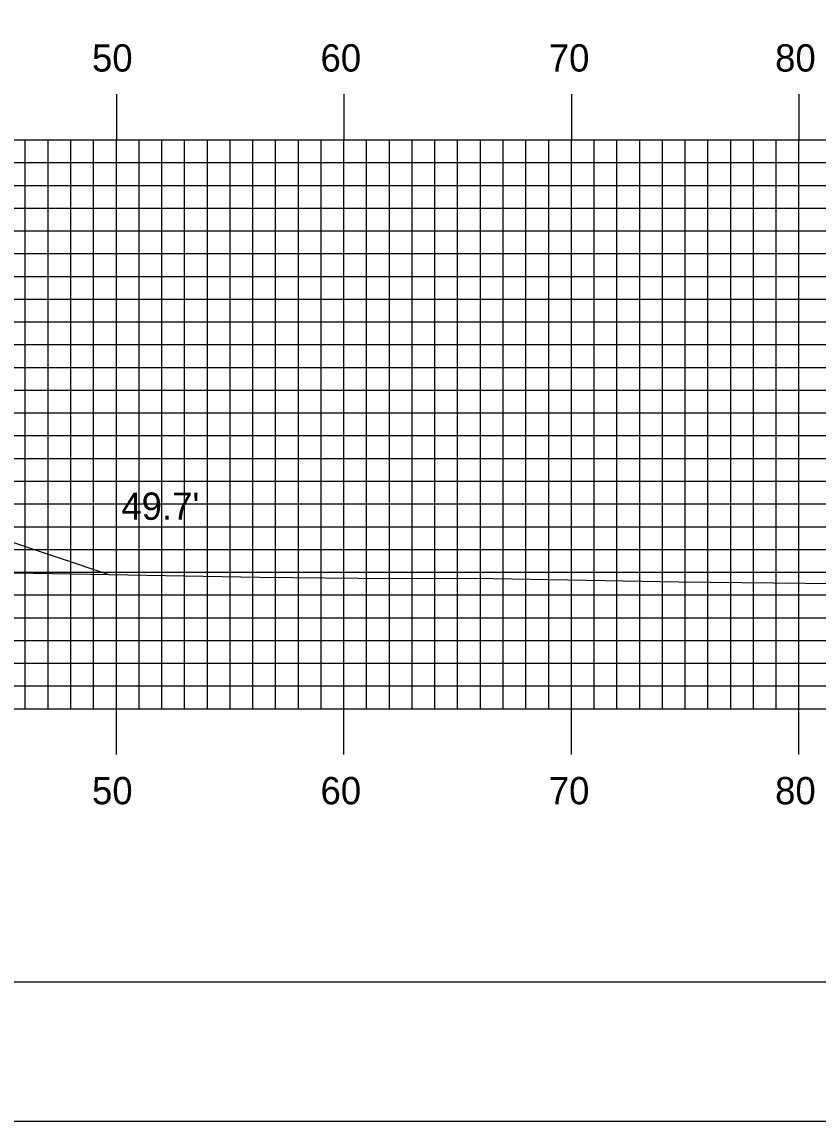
# Model space of a CAD drawing. Extents: x 856323 to 856666, y 364765 to 364985.
# Drawn here: x 856534.62 to 856569.6, y 364765.18 to 364813.48 of the extents above; entities that cross this region are included whole.
import ezdxf

# ---------------------------------------------------------------- set-up
doc = ezdxf.new("R2010")
doc.units = 0
for name, color, linetype in [('BORDER', 7, 'Continuous'), ('D_Roadway_Centerline', 7, 'Continuous'), ('D_Roadway_SlopeLines', 7, 'Continuous'), ('D_Text_Standard', 7, 'Continuous'), ('H_V ANNOTATION', 7, 'Continuous'), ('MAJOR', 7, 'Continuous'), ('MINOR', 7, 'Continuous'), ('PLOT BOUNDARY', 7, 'Continuous'), ('S_Roadway_Centerline', 7, 'Continuous')]:
    doc.layers.add(name, color=color, linetype=linetype)

msp = doc.modelspace()

# ---------------------------------------------------------------- linework, layer by layer
at = {"layer": 'BORDER'}
msp.add_lwpolyline([(856339.168, 364771.302), (856659.168, 364771.302), (856659.168, 364981.302), (856339.168, 364981.302)], close=True, dxfattribs=at)
at = {"layer": 'D_Roadway_Centerline'}
msp.add_lwpolyline([(856476.768, 364802.881), (856476.768, 364802.881), (856488.768, 364802.411), (856496.768, 364802.091), (856508.768, 364799.091), (856509.389, 364798.935), (856538.439, 364789.201), (856538.441, 364789.2)], dxfattribs=at)
at = {"layer": 'D_Roadway_SlopeLines'}
msp.add_lwpolyline([(856496.768, 364802.091), (856509.389, 364798.935), (856538.441, 364789.2)], dxfattribs=at)
at = {"layer": 'MAJOR'}
for p, q in [((856538.768, 364810.306), (856538.768, 364808.302)), ((856548.768, 364810.306), (856548.768, 364808.302)), ((856558.768, 364810.306), (856558.768, 364808.302)), ((856568.768, 364810.306), (856568.768, 364808.302)), ((856348.768, 364808.302), (856628.768, 364808.302)), ((856348.768, 364808.302), (856628.768, 364808.302)), ((856538.768, 364783.302), (856538.768, 364808.302)), ((856548.768, 364783.302), (856548.768, 364808.302)), ((856558.768, 364783.302), (856558.768, 364808.302)), ((856568.768, 364783.302), (856568.768, 364808.302)), ((856348.768, 364803.302), (856628.768, 364803.302)), ((856348.768, 364798.302), (856628.768, 364798.302)), ((856348.768, 364793.302), (856628.768, 364793.302)), ((856348.768, 364788.302), (856628.768, 364788.302)), ((856348.768, 364783.302), (856628.768, 364783.302)), ((856348.768, 364783.302), (856628.768, 364783.302)), ((856538.768, 364781.298), (856538.768, 364783.302)), ((856548.768, 364781.298), (856548.768, 364783.302)), ((856558.768, 364781.298), (856558.768, 364783.302)), ((856568.768, 364781.298), (856568.768, 364783.302))]:
    msp.add_line(p, q, dxfattribs=at)
at = {"layer": 'MINOR'}
for p, q in [((856534.768, 364783.302), (856534.768, 364808.302)), ((856535.768, 364783.302), (856535.768, 364808.302)), ((856536.768, 364783.302), (856536.768, 364808.302)), ((856537.768, 364783.302), (856537.768, 364808.302)), ((856539.768, 364783.302), (856539.768, 364808.302)), ((856540.768, 364783.302), (856540.768, 364808.302)), ((856541.768, 364783.302), (856541.768, 364808.302)), ((856542.768, 364783.302), (856542.768, 364808.302)), ((856543.768, 364783.302), (856543.768, 364808.302)), ((856544.768, 364783.302), (856544.768, 364808.302)), ((856545.768, 364783.302), (856545.768, 364808.302)), ((856546.768, 364783.302), (856546.768, 364808.302)), ((856547.768, 364783.302), (856547.768, 364808.302)), ((856549.768, 364783.302), (856549.768, 364808.302)), ((856550.768, 364783.302), (856550.768, 364808.302)), ((856551.768, 364783.302), (856551.768, 364808.302)), ((856552.768, 364783.302), (856552.768, 364808.302)), ((856553.768, 364783.302), (856553.768, 364808.302)), ((856554.768, 364783.302), (856554.768, 364808.302)), ((856555.768, 364783.302), (856555.768, 364808.302)), ((856556.768, 364783.302), (856556.768, 364808.302)), ((856557.768, 364783.302), (856557.768, 364808.302)), ((856559.768, 364783.302), (856559.768, 364808.302)), ((856560.768, 364783.302), (856560.768, 364808.302)), ((856561.768, 364783.302), (856561.768, 364808.302)), ((856562.768, 364783.302), (856562.768, 364808.302)), ((856563.768, 364783.302), (856563.768, 364808.302)), ((856564.768, 364783.302), (856564.768, 364808.302)), ((856565.768, 364783.302), (856565.768, 364808.302)), ((856566.768, 364783.302), (856566.768, 364808.302)), ((856567.768, 364783.302), (856567.768, 364808.302)), ((856348.768, 364807.302), (856628.768, 364807.302)), ((856348.768, 364806.302), (856628.768, 364806.302)), ((856348.768, 364805.302), (856628.768, 364805.302)), ((856348.768, 364804.302), (856628.768, 364804.302)), ((856348.768, 364802.302), (856628.768, 364802.302)), ((856348.768, 364801.302), (856628.768, 364801.302)), ((856348.768, 364800.302), (856628.768, 364800.302)), ((856348.768, 364799.302), (856628.768, 364799.302)), ((856348.768, 364797.302), (856628.768, 364797.302)), ((856348.768, 364796.302), (856628.768, 364796.302)), ((856348.768, 364795.302), (856628.768, 364795.302)), ((856348.768, 364794.302), (856628.768, 364794.302)), ((856348.768, 364792.302), (856628.768, 364792.302)), ((856348.768, 364791.302), (856628.768, 364791.302)), ((856348.768, 364790.302), (856628.768, 364790.302)), ((856348.768, 364789.302), (856628.768, 364789.302)), ((856348.768, 364787.302), (856628.768, 364787.302)), ((856348.768, 364786.302), (856628.768, 364786.302)), ((856348.768, 364785.302), (856628.768, 364785.302)), ((856348.768, 364784.302), (856628.768, 364784.302))]:
    msp.add_line(p, q, dxfattribs=at)
at = {"layer": 'PLOT BOUNDARY'}
msp.add_lwpolyline([(856322.982, 364765.184), (856662.982, 364765.184), (856662.982, 364985.184), (856322.982, 364985.184)], close=True, dxfattribs=at)
at = {"layer": 'S_Roadway_Centerline'}
msp.add_lwpolyline([(856467.245, 364789.883), (856481.397, 364789.741), (856490.903, 364789.576), (856496.772, 364789.408), (856503.027, 364789.391), (856512.402, 364789.138), (856516.046, 364789.126), (856526.862, 364789.385), (856535.128, 364789.259), (856545.068, 364789.082), (856550.824, 364789.019), (856554.531, 364789.035), (856563.493, 364788.873), (856574.574, 364788.764), (856575.241, 364788.768), (856576.228, 364788.745), (856592.678, 364788.737), (856598.386, 364788.819), (856608.798, 364788.494), (856611.234, 364788.396), (856612.656, 364788.381), (856621.756, 364788.461), (856628.768, 364788.505)], dxfattribs=at)

# ---------------------------------------------------------------- texts
at = {"layer": 'D_Text_Standard'}
msp.add_text("49.7'", height=1.2, dxfattribs=at).set_placement((856538.988, 364791.604))
at = {"layer": 'H_V ANNOTATION'}
for s, p in [('50', (856537.698, 364811.302)), ('60', (856547.741, 364811.302)), ('70', (856557.773, 364811.302)), ('80', (856567.719, 364811.302)), ('50', (856537.698, 364779.102)), ('60', (856547.741, 364779.102)), ('70', (856557.773, 364779.102)), ('80', (856567.719, 364779.102))]:
    msp.add_text(s, height=1.2, dxfattribs=at).set_placement(p)

doc.saveas('drawing.dxf')
